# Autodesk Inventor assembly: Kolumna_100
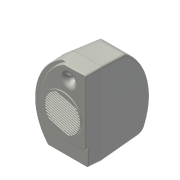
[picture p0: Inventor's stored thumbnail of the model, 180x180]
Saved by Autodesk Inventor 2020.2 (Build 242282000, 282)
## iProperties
Created: 2010-12
Part Number: Kolumna_100
Document SubType Name: Assembly
Designer: F.Stasiak
Manager: www.cadconsulting.pl
Company: Fabian Stasiak CAD Consulting
Author: F.Stasiak
Subject: Zbiór ćwiczeń. Autodesk Inventor 2020. Kurs podstawowy
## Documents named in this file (3)
- C:\2020_Kurs_podstawowy\R5 Części\Elementy\Kolumna_100.iam
- C:\2020_Kurs_podstawowy\R5 Części\Elementy\Tył_kolumny_100.ipt
- C:\2020_Kurs_podstawowy\R5 Części\Elementy\Front_kolumny_100.ipt
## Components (2 placed, 2 different names)
1. Tył_kolumny_100:1 — Zestawiający:1, Zestawiający:2, Zestawiający:3
2. Front_kolumny_100:1 — Zestawiający:1, Zestawiający:2, Zestawiający:3
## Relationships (3: Mate 3)
- Zestawiający:1 [Mate]: Tył_kolumny_100:1 ↔ Front_kolumny_100:1
- Zestawiający:2 [Mate]: Tył_kolumny_100:1 ↔ Front_kolumny_100:1
- Zestawiający:3 [Mate]: Tył_kolumny_100:1 ↔ Front_kolumny_100:1
